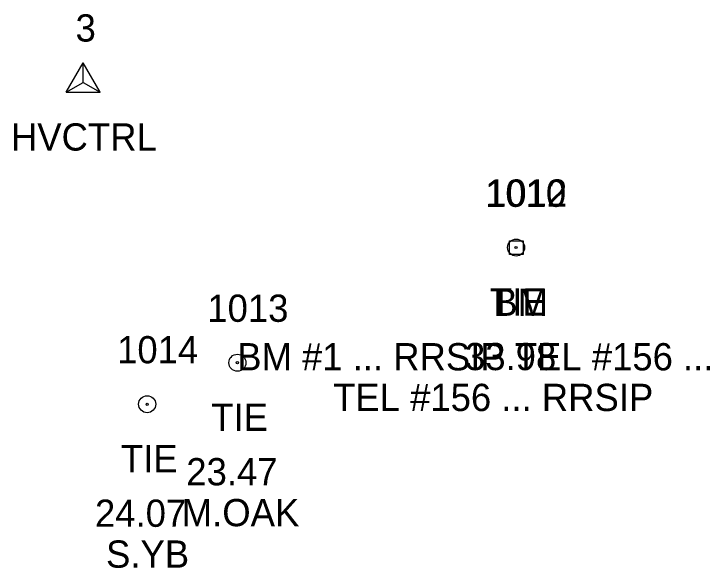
# Model space of a CAD drawing. Extents: x 1588028 to 1589597, y 137576 to 138176.
# Drawn here: x 1588028.3 to 1588079.4, y 137878.3 to 137919 of the extents above; entities that cross this region are included whole.
import ezdxf

# ---------------------------------------------------------------- set-up
doc = ezdxf.new("R2010")
doc.units = 0
for name, color, linetype in [('C_A', 7, 'Continuous'), ('C_C', 7, 'Continuous'), ('C_I', 7, 'Continuous'), ('CBP', 7, 'Continuous'), ('CPBM', 7, 'Continuous'), ('CPSM', 7, 'Continuous')]:
    doc.layers.add(name, color=color, linetype=linetype)

msp = doc.modelspace()

# ---------------------------------------------------------------- linework, layer by layer
at = {"layer": 'CBP'}
for centre, radius in [((1588065.17, 137901.867), 0.625), ((1588065.17, 137901.867), 0.0833), ((1588044.726, 137893.413), 0.625), ((1588044.726, 137893.413), 0.0833), ((1588038.108, 137890.368), 0.625), ((1588038.108, 137890.368), 0.0833)]:
    msp.add_circle(centre, radius, dxfattribs=at)
at = {"layer": 'CPBM'}
for p, q in [((1588064.681, 137901.35), (1588064.681, 137902.35)), ((1588064.681, 137902.35), (1588065.681, 137902.35)), ((1588065.681, 137902.35), (1588065.681, 137901.35)), ((1588065.184, 137901.851), (1588065.184, 137901.851)), ((1588065.184, 137901.851), (1588065.184, 137901.851)), ((1588065.681, 137901.35), (1588064.681, 137901.35))]:
    msp.add_line(p, q, dxfattribs=at)
at = {"layer": 'CPSM'}
for p, q in [((1588032.172, 137913.262), (1588033.422, 137915.427)), ((1588034.672, 137913.262), (1588033.422, 137915.427)), ((1588033.422, 137913.983), (1588033.422, 137915.427)), ((1588032.172, 137913.262), (1588033.422, 137913.983)), ((1588033.422, 137913.983), (1588033.422, 137913.983)), ((1588033.422, 137913.983), (1588034.672, 137913.262)), ((1588032.172, 137913.262), (1588034.672, 137913.262))]:
    msp.add_line(p, q, dxfattribs=at)

# ---------------------------------------------------------------- texts
at = {"layer": 'C_A'}
for s, p in [('HVCTRL', (1588028.115, 137908.983)), ('TIE', (1588063.249, 137896.867)), ('BM', (1588063.499, 137896.851)), ('TIE', (1588042.805, 137888.413)), ('TIE', (1588036.187, 137885.368))]:
    msp.add_text(s, height=2, dxfattribs=at).set_placement(p)
at = {"layer": 'C_C'}
for s, p in [('BM #1 ... RRSIP TEL #156 ...', (1588044.712, 137892.851)), ('33.98', (1588061.422, 137892.867)), ('TEL #156 ... RRSIP', (1588051.745, 137889.867)), ('23.47', (1588040.978, 137884.413)), ('24.07', (1588034.281, 137881.368)), ('M.OAK', (1588040.647, 137881.413)), ('S.YB', (1588035.092, 137878.368))]:
    msp.add_text(s, height=2, dxfattribs=at).set_placement(p)
at = {"layer": 'C_I'}
for s, p in [('3', (1588032.855, 137916.983)), ('1010', (1588062.893, 137904.851)), ('1012', (1588062.965, 137904.867)), ('1013', (1588042.521, 137896.413)), ('1014', (1588035.903, 137893.368))]:
    msp.add_text(s, height=2, dxfattribs=at).set_placement(p)

doc.saveas('drawing.dxf')
